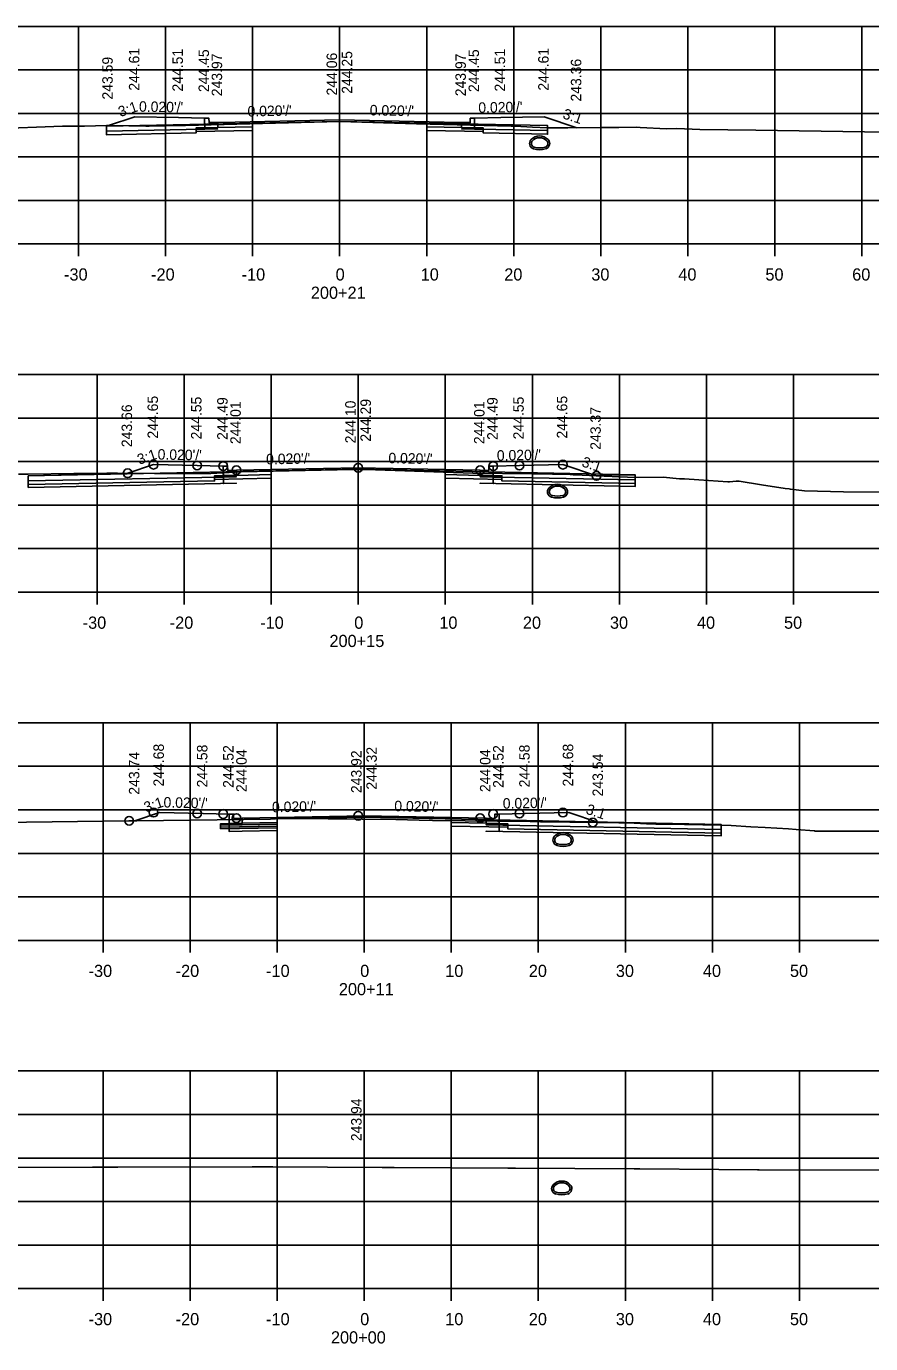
# Model space of a CAD drawing. Extents: x 1369627 to 1374022, y 380035 to 398173.
# Drawn here: x 1372516.6 to 1372613.6, y 380056.4 to 380207.8 of the extents above; entities that cross this region are included whole.
import ezdxf

# ---------------------------------------------------------------- set-up
doc = ezdxf.new("R2010")
doc.units = 0
for name, color, linetype in [('Default', 7, 'Continuous'), ('R_Alt Surface', 7, 'Continuous'), ('R_Axis', 7, 'Continuous'), ('R_Axis Annot', 7, 'Continuous'), ('R_Drive', 7, 'Continuous'), ('R_Exist Surface', 7, 'Continuous'), ('R_Fin Surface', 7, 'Continuous'), ('R_Grid', 7, 'Continuous'), ('R_No Plot', 7, 'Continuous'), ('R_Xsect Elev', 7, 'Continuous'), ('R_Xsect Slope', 7, 'Continuous')]:
    doc.layers.add(name, color=color, linetype=linetype)

msp = doc.modelspace()

# ---------------------------------------------------------------- linework, layer by layer
at = {"layer": 'Default'}
for points in [[(1372537.09, 380197.21), (1372537.59, 380197.21), (1372537.6, 380196.71), (1372538.6, 380196.73), (1372538.6, 380196.14), (1372537.1, 380196.11)], [(1372567.6, 380196.71), (1372567.61, 380197.21), (1372568.11, 380197.21), (1372568.1, 380196.11), (1372566.6, 380196.14), (1372566.6, 380196.73)], [(1372539.23, 380157.25), (1372539.73, 380157.25), (1372539.74, 380156.75), (1372540.74, 380156.77), (1372540.74, 380156.18), (1372539.24, 380156.15)], [(1372569.74, 380156.75), (1372569.75, 380157.25), (1372570.25, 380157.25), (1372570.24, 380156.15), (1372568.74, 380156.18), (1372568.74, 380156.77)], [(1372539.91, 380117.28), (1372540.41, 380117.28), (1372540.42, 380116.78), (1372541.42, 380116.8), (1372541.42, 380116.21), (1372539.92, 380116.18)], [(1372570.42, 380116.78), (1372570.43, 380117.28), (1372570.93, 380117.28), (1372570.92, 380116.18), (1372569.42, 380116.21), (1372569.42, 380116.8)]]:
    msp.add_lwpolyline(points, close=True, dxfattribs=at)
at = {"layer": 'R_Alt Surface'}
for points in [[(1372537.09, 380197.21), (1372537.1, 380195.94), (1372538.6, 380195.97), (1372525.81, 380195.72), (1372525.81, 380196.3), (1372552.6, 380196.84), (1372576.48, 380196.36), (1372576.48, 380195.78), (1372566.6, 380195.97), (1372568.1, 380195.94), (1372568.11, 380197.21)], [(1372537.09, 380197.21), (1372537.1, 380196.11), (1372538.6, 380196.14), (1372542.6, 380196.22), (1372542.6, 380196.64), (1372552.6, 380196.84), (1372562.6, 380196.64), (1372562.6, 380196.22), (1372566.6, 380196.14), (1372568.1, 380196.11), (1372568.11, 380197.21)], [(1372539.23, 380157.25), (1372539.24, 380155.24), (1372540.74, 380155.27), (1372516.83, 380154.79), (1372516.83, 380156.12), (1372554.74, 380156.88), (1372586.55, 380156.24), (1372586.55, 380154.91), (1372568.74, 380155.27), (1372570.24, 380155.24), (1372570.25, 380157.25)], [(1372539.23, 380157.25), (1372539.24, 380155.99), (1372540.74, 380156.02), (1372516.83, 380155.54), (1372516.83, 380156.12), (1372554.74, 380156.88), (1372586.55, 380156.24), (1372586.55, 380155.66), (1372568.74, 380156.02), (1372570.24, 380155.99), (1372570.25, 380157.25)], [(1372539.23, 380157.25), (1372539.24, 380156.15), (1372540.74, 380156.18), (1372544.74, 380156.26), (1372544.74, 380156.68), (1372554.74, 380156.88), (1372564.74, 380156.68), (1372564.74, 380156.26), (1372568.74, 380156.18), (1372570.24, 380156.15), (1372570.25, 380157.25)], [(1372539.91, 380117.28), (1372539.92, 380115.27), (1372541.42, 380115.3), (1372545.42, 380115.38), (1372545.42, 380116.71), (1372555.42, 380116.91), (1372596.41, 380116.09), (1372596.41, 380114.76), (1372569.42, 380115.3), (1372570.92, 380115.27), (1372570.93, 380117.28)], [(1372539.91, 380117.28), (1372539.92, 380116.02), (1372541.42, 380116.05), (1372545.42, 380116.13), (1372545.42, 380116.71), (1372555.42, 380116.91), (1372596.41, 380116.09), (1372596.41, 380115.51), (1372569.42, 380116.05), (1372570.92, 380116.02), (1372570.93, 380117.28)], [(1372539.91, 380117.28), (1372539.92, 380116.18), (1372541.42, 380116.21), (1372545.42, 380116.29), (1372545.42, 380116.71), (1372555.42, 380116.91), (1372565.42, 380116.71), (1372565.42, 380116.29), (1372569.42, 380116.21), (1372570.92, 380116.18), (1372570.93, 380117.28)]]:
    msp.add_lwpolyline(points, dxfattribs=at)
for points in [[(1372525.81, 380195.72), (1372538.6, 380195.97), (1372537.1, 380195.94), (1372536.1, 380195.92), (1372536.1, 380195.51), (1372525.81, 380195.3)], [(1372542.6, 380196.22), (1372538.6, 380196.14), (1372537.1, 380196.11), (1372536.1, 380196.09), (1372536.1, 380195.67), (1372542.6, 380195.8)], [(1372552.6, 380197.01), (1372540.6, 380196.77), (1372538.6, 380196.73), (1372538.6, 380196.14), (1372542.6, 380196.22), (1372542.6, 380196.64), (1372552.6, 380196.84), (1372562.6, 380196.64), (1372562.6, 380196.22), (1372566.6, 380196.14), (1372566.6, 380196.73), (1372564.6, 380196.77)], [(1372562.6, 380196.22), (1372566.6, 380196.14), (1372568.1, 380196.11), (1372569.1, 380196.09), (1372569.1, 380195.67), (1372562.6, 380195.8)], [(1372576.48, 380195.78), (1372566.6, 380195.97), (1372568.1, 380195.94), (1372569.1, 380195.92), (1372569.1, 380195.51), (1372576.48, 380195.36)], [(1372554.74, 380157.05), (1372542.74, 380156.81), (1372540.74, 380156.77), (1372540.74, 380156.18), (1372544.74, 380156.26), (1372544.74, 380156.68), (1372554.74, 380156.88), (1372564.74, 380156.68), (1372564.74, 380156.26), (1372568.74, 380156.18), (1372568.74, 380156.77), (1372566.74, 380156.81)], [(1372516.83, 380155.54), (1372540.74, 380156.02), (1372539.24, 380155.99), (1372538.24, 380155.97), (1372538.24, 380155.55), (1372516.83, 380155.12)], [(1372544.74, 380156.26), (1372540.74, 380156.18), (1372539.24, 380156.15), (1372538.24, 380156.13), (1372538.24, 380155.72), (1372544.74, 380155.85)], [(1372564.74, 380156.26), (1372568.74, 380156.18), (1372570.24, 380156.15), (1372571.24, 380156.13), (1372571.24, 380155.72), (1372564.74, 380155.85)], [(1372586.55, 380155.66), (1372568.74, 380156.02), (1372570.24, 380155.99), (1372571.24, 380155.97), (1372571.24, 380155.55), (1372586.55, 380155.24)], [(1372555.42, 380117.08), (1372543.42, 380116.84), (1372541.42, 380116.8), (1372541.42, 380116.21), (1372545.42, 380116.29), (1372545.42, 380116.71), (1372555.42, 380116.91), (1372565.42, 380116.71), (1372565.42, 380116.29), (1372569.42, 380116.21), (1372569.42, 380116.8), (1372567.42, 380116.84)], [(1372545.42, 380116.29), (1372541.42, 380116.21), (1372539.92, 380116.18), (1372538.92, 380116.16), (1372538.92, 380115.75), (1372545.42, 380115.88)], [(1372545.42, 380116.13), (1372541.42, 380116.05), (1372539.92, 380116.02), (1372538.92, 380116), (1372538.92, 380115.58), (1372545.42, 380115.71)], [(1372565.42, 380116.29), (1372569.42, 380116.21), (1372570.92, 380116.18), (1372571.92, 380116.16), (1372571.92, 380115.75), (1372565.42, 380115.88)], [(1372596.41, 380115.51), (1372569.42, 380116.05), (1372570.92, 380116.02), (1372571.92, 380116), (1372571.92, 380115.58), (1372596.41, 380115.09)]]:
    msp.add_lwpolyline(points, close=True, dxfattribs=at)
at = {"layer": 'R_Axis'}
for p, q in [((1372402.6, 380182.76), (1372702.6, 380182.76)), ((1372522.6, 380181.36), (1372522.6, 380182.76)), ((1372532.6, 380181.36), (1372532.6, 380182.76)), ((1372542.6, 380181.36), (1372542.6, 380182.76)), ((1372552.6, 380181.36), (1372552.6, 380182.76)), ((1372562.6, 380181.36), (1372562.6, 380182.76)), ((1372572.6, 380181.36), (1372572.6, 380182.76)), ((1372582.6, 380181.36), (1372582.6, 380182.76)), ((1372592.6, 380181.36), (1372592.6, 380182.76)), ((1372602.6, 380181.36), (1372602.6, 380182.76)), ((1372612.6, 380181.36), (1372612.6, 380182.76)), ((1372404.74, 380142.76), (1372704.74, 380142.76)), ((1372524.74, 380141.36), (1372524.74, 380142.76)), ((1372534.74, 380141.36), (1372534.74, 380142.76)), ((1372544.74, 380141.36), (1372544.74, 380142.76)), ((1372554.74, 380141.36), (1372554.74, 380142.76)), ((1372564.74, 380141.36), (1372564.74, 380142.76)), ((1372574.74, 380141.36), (1372574.74, 380142.76)), ((1372584.74, 380141.36), (1372584.74, 380142.76)), ((1372594.74, 380141.36), (1372594.74, 380142.76)), ((1372604.74, 380141.36), (1372604.74, 380142.76)), ((1372405.42, 380102.76), (1372705.42, 380102.76)), ((1372525.42, 380101.36), (1372525.42, 380102.76)), ((1372535.42, 380101.36), (1372535.42, 380102.76)), ((1372545.42, 380101.36), (1372545.42, 380102.76)), ((1372555.42, 380101.36), (1372555.42, 380102.76)), ((1372565.42, 380101.36), (1372565.42, 380102.76)), ((1372575.42, 380101.36), (1372575.42, 380102.76)), ((1372585.42, 380101.36), (1372585.42, 380102.76)), ((1372595.42, 380101.36), (1372595.42, 380102.76)), ((1372605.42, 380101.36), (1372605.42, 380102.76)), ((1372405.42, 380062.76), (1372705.42, 380062.76)), ((1372525.42, 380061.36), (1372525.42, 380062.76)), ((1372535.42, 380061.36), (1372535.42, 380062.76)), ((1372545.42, 380061.36), (1372545.42, 380062.76)), ((1372555.42, 380061.36), (1372555.42, 380062.76)), ((1372565.42, 380061.36), (1372565.42, 380062.76)), ((1372575.42, 380061.36), (1372575.42, 380062.76)), ((1372585.42, 380061.36), (1372585.42, 380062.76)), ((1372595.42, 380061.36), (1372595.42, 380062.76)), ((1372605.42, 380061.36), (1372605.42, 380062.76))]:
    msp.add_line(p, q, dxfattribs=at)
at = {"layer": 'R_Drive'}
for centre, radius, start, end in [((1372575.06, 380194.31), 0.646, 136.3515, 253.9529), ((1372575.57, 380193.82), 1.35, 43.6485, 136.3515), ((1372575.06, 380194.31), 0.438, 136.3515, 253.9529), ((1372575.57, 380193.82), 1.15, 43.6485, 136.3515), ((1372576.09, 380194.31), 0.438, 286.0471, 43.6485), ((1372576.09, 380194.31), 0.646, 286.0471, 43.6485), ((1372575.57, 380196.09), 2.5, 253.9529, 286.0471), ((1372575.57, 380196.09), 2.29, 253.9529, 286.0471), ((1372577.63, 380153.8), 1.35, 43.6485, 136.3515), ((1372577.63, 380153.8), 1.15, 43.6485, 136.3515), ((1372577.12, 380154.29), 0.646, 136.3515, 253.9529), ((1372577.12, 380154.29), 0.438, 136.3515, 253.9529), ((1372577.63, 380156.08), 2.5, 253.9529, 286.0471), ((1372577.63, 380156.08), 2.29, 253.9529, 286.0471), ((1372578.14, 380154.29), 0.438, 286.0471, 43.6485), ((1372578.14, 380154.29), 0.646, 286.0471, 43.6485), ((1372577.75, 380114.28), 0.646, 136.3515, 253.9529), ((1372578.26, 380113.79), 1.35, 43.6485, 136.3515), ((1372577.75, 380114.28), 0.438, 136.3515, 253.9529), ((1372578.26, 380113.79), 1.15, 43.6485, 136.3515), ((1372578.77, 380114.28), 0.438, 286.0471, 43.6485), ((1372578.77, 380114.28), 0.646, 286.0471, 43.6485), ((1372578.26, 380116.06), 2.5, 253.9529, 286.0471), ((1372578.26, 380116.06), 2.29, 253.9529, 286.0471), ((1372577.6, 380074.25), 0.646, 136.3515, 253.9529), ((1372578.12, 380073.77), 1.35, 43.6485, 136.3515), ((1372578.12, 380073.77), 1.15, 43.6485, 136.3515), ((1372578.63, 380074.25), 0.646, 286.0471, 43.6485), ((1372577.6, 380074.25), 0.438, 136.3515, 253.9529), ((1372578.12, 380076.04), 2.5, 253.9529, 286.0471), ((1372578.12, 380076.04), 2.29, 253.9529, 286.0471), ((1372578.63, 380074.25), 0.438, 286.0471, 43.6485)]:
    msp.add_arc(centre, radius, start, end, dxfattribs=at)
at = {"layer": 'R_Exist Surface'}
for points in [[(1372512.73, 380196), (1372520.78, 380196.28), (1372521.71, 380196.29), (1372522.25, 380196.3), (1372523.27, 380196.31), (1372525.81, 380196.35), (1372526.44, 380196.35), (1372530.33, 380196.28), (1372530.71, 380196.29), (1372534.29, 380196.35), (1372534.44, 380196.35), (1372534.5, 380196.35), (1372534.89, 380196.36), (1372552.62, 380196.82), (1372560.16, 380196.61), (1372561.43, 380196.57), (1372572.3, 380196.31), (1372572.77, 380196.28), (1372574.75, 380196.18), (1372576.48, 380196.1), (1372578.8, 380196.11), (1372582.55, 380196.13), (1372584.16, 380196.14), (1372584.69, 380196.14), (1372586.69, 380196.16), (1372587.11, 380196.13), (1372590.13, 380195.99), (1372591.34, 380196.02), (1372593.96, 380195.9), (1372600.42, 380195.85), (1372612.91, 380195.65), (1372621.12, 380195.62)], [(1372515.69, 380156.3), (1372516.83, 380156.33), (1372522.07, 380156.38), (1372524.83, 380156.41), (1372525.86, 380156.42), (1372527.07, 380156.43), (1372531.33, 380156.39), (1372534.71, 380156.37), (1372537.79, 380156.41), (1372541.27, 380156.57), (1372554.16, 380156.85), (1372554.74, 380156.86), (1372554.96, 380156.85), (1372555, 380156.85), (1372555.62, 380156.84), (1372567.89, 380156.44), (1372574.68, 380156.35), (1372574.98, 380156.35), (1372579.07, 380156.28), (1372579.42, 380156.24), (1372580.47, 380156.19), (1372582.11, 380156.12), (1372585.67, 380155.99), (1372586.55, 380155.95), (1372589.78, 380155.96), (1372591.64, 380155.8), (1372591.93, 380155.8), (1372592.02, 380155.79), (1372592.23, 380155.78), (1372593.88, 380155.66), (1372597.18, 380155.45), (1372597.4, 380155.45), (1372598.17, 380155.53), (1372598.48, 380155.51), (1372601.08, 380155.11), (1372603.77, 380154.68), (1372604.23, 380154.64), (1372604.38, 380154.59), (1372605.99, 380154.39), (1372610.5, 380154.3), (1372625.69, 380154.25)], [(1372513.67, 380116.29), (1372528.4, 380116.49), (1372529.13, 380116.5), (1372529.2, 380116.5), (1372529.22, 380116.5), (1372529.23, 380116.5), (1372529.24, 380116.5), (1372529.28, 380116.5), (1372529.31, 380116.5), (1372544.66, 380116.7), (1372545.22, 380116.73), (1372547.41, 380116.77), (1372559.06, 380116.64), (1372561.73, 380116.56), (1372563.26, 380116.53), (1372574.5, 380116.4), (1372575.68, 380116.38), (1372585.76, 380116.26), (1372587.85, 380116.17), (1372588.91, 380116.13), (1372590.42, 380116.1), (1372592.21, 380116.06), (1372596.41, 380116.01), (1372597.57, 380115.95), (1372599.83, 380115.81), (1372601.48, 380115.73), (1372604.15, 380115.57), (1372605.05, 380115.5), (1372607.15, 380115.33), (1372607.24, 380115.3), (1372619.73, 380115.32)], [(1372509.33, 380076.69), (1372524.19, 380076.73), (1372527.13, 380076.73), (1372542.55, 380076.76), (1372544.92, 380076.76), (1372557.5, 380076.69), (1372558.85, 380076.68), (1372571.94, 380076.6), (1372572.79, 380076.59), (1372586.42, 380076.51), (1372586.77, 380076.51), (1372587.1, 380076.51), (1372596.15, 380076.46), (1372600.59, 380076.42), (1372600.78, 380076.42), (1372614.61, 380076.36)]]:
    msp.add_lwpolyline(points, dxfattribs=at)
at = {"layer": 'R_Fin Surface'}
for points in [[(1372525.81, 380196.3), (1372526.03, 380196.35), (1372529.09, 380197.37), (1372534.09, 380197.27), (1372537.09, 380197.21), (1372537.59, 380197.21), (1372537.6, 380196.71), (1372538.6, 380196.73), (1372540.6, 380196.77), (1372552.6, 380197.01), (1372564.6, 380196.77), (1372566.6, 380196.73), (1372567.6, 380196.71), (1372567.61, 380197.21), (1372568.11, 380197.21), (1372571.11, 380197.27), (1372576.11, 380197.37), (1372579.86, 380196.12)], [(1372516.83, 380156.12), (1372522.05, 380156.25), (1372523.09, 380156.28), (1372525.64, 380156.35), (1372526.16, 380156.36), (1372526.6, 380156.37), (1372527.73, 380156.4), (1372528.25, 380156.42), (1372531.23, 380157.41), (1372536.23, 380157.31), (1372539.23, 380157.25), (1372539.73, 380157.25), (1372539.74, 380156.75), (1372540.74, 380156.77), (1372542.74, 380156.81), (1372554.74, 380157.05), (1372566.74, 380156.81), (1372568.74, 380156.77), (1372569.74, 380156.75), (1372569.75, 380157.25), (1372570.25, 380157.25), (1372573.25, 380157.31), (1372578.25, 380157.41), (1372582.1, 380156.12), (1372582.48, 380156.16), (1372583.12, 380156.23), (1372586.55, 380156.24)], [(1372529.09, 380116.5), (1372531.91, 380117.44), (1372536.91, 380117.34), (1372539.91, 380117.28), (1372540.41, 380117.28), (1372540.42, 380116.78), (1372541.42, 380116.8), (1372543.42, 380116.84), (1372555.42, 380117.08), (1372567.42, 380116.84), (1372569.42, 380116.8), (1372570.42, 380116.78), (1372570.43, 380117.28), (1372570.93, 380117.28), (1372573.93, 380117.34), (1372578.93, 380117.44), (1372582.35, 380116.3), (1372596.41, 380116.09)]]:
    msp.add_lwpolyline(points, dxfattribs=at)
at = {"layer": 'R_Grid'}
for p, q in [((1372402.6, 380207.76), (1372702.6, 380207.76)), ((1372522.6, 380182.76), (1372522.6, 380207.76)), ((1372532.6, 380182.76), (1372532.6, 380207.76)), ((1372542.6, 380182.76), (1372542.6, 380207.76)), ((1372552.6, 380182.76), (1372552.6, 380207.76)), ((1372562.6, 380182.76), (1372562.6, 380207.76)), ((1372572.6, 380182.76), (1372572.6, 380207.76)), ((1372582.6, 380182.76), (1372582.6, 380207.76)), ((1372592.6, 380182.76), (1372592.6, 380207.76)), ((1372602.6, 380182.76), (1372602.6, 380207.76)), ((1372612.6, 380182.76), (1372612.6, 380207.76)), ((1372402.6, 380202.76), (1372702.6, 380202.76)), ((1372402.6, 380197.76), (1372702.6, 380197.76)), ((1372402.6, 380192.76), (1372702.6, 380192.76)), ((1372402.6, 380187.76), (1372702.6, 380187.76)), ((1372402.6, 380182.76), (1372702.6, 380182.76)), ((1372404.74, 380167.76), (1372704.74, 380167.76)), ((1372524.74, 380142.76), (1372524.74, 380167.76)), ((1372534.74, 380142.76), (1372534.74, 380167.76)), ((1372544.74, 380142.76), (1372544.74, 380167.76)), ((1372554.74, 380142.76), (1372554.74, 380167.76)), ((1372564.74, 380142.76), (1372564.74, 380167.76)), ((1372574.74, 380142.76), (1372574.74, 380167.76)), ((1372584.74, 380142.76), (1372584.74, 380167.76)), ((1372594.74, 380142.76), (1372594.74, 380167.76)), ((1372604.74, 380142.76), (1372604.74, 380167.76)), ((1372404.74, 380162.76), (1372704.74, 380162.76)), ((1372404.74, 380157.76), (1372704.74, 380157.76)), ((1372404.74, 380152.76), (1372704.74, 380152.76)), ((1372404.74, 380147.76), (1372704.74, 380147.76)), ((1372404.74, 380142.76), (1372704.74, 380142.76)), ((1372405.42, 380127.76), (1372705.42, 380127.76)), ((1372525.42, 380102.76), (1372525.42, 380127.76)), ((1372535.42, 380102.76), (1372535.42, 380127.76)), ((1372545.42, 380102.76), (1372545.42, 380127.76)), ((1372555.42, 380102.76), (1372555.42, 380127.76)), ((1372565.42, 380102.76), (1372565.42, 380127.76)), ((1372575.42, 380102.76), (1372575.42, 380127.76)), ((1372585.42, 380102.76), (1372585.42, 380127.76)), ((1372595.42, 380102.76), (1372595.42, 380127.76)), ((1372605.42, 380102.76), (1372605.42, 380127.76)), ((1372405.42, 380122.76), (1372705.42, 380122.76)), ((1372405.42, 380117.76), (1372705.42, 380117.76)), ((1372405.42, 380112.76), (1372705.42, 380112.76)), ((1372405.42, 380107.76), (1372705.42, 380107.76)), ((1372405.42, 380102.76), (1372705.42, 380102.76)), ((1372405.42, 380087.76), (1372705.42, 380087.76)), ((1372525.42, 380062.76), (1372525.42, 380087.76)), ((1372535.42, 380062.76), (1372535.42, 380087.76)), ((1372545.42, 380062.76), (1372545.42, 380087.76)), ((1372555.42, 380062.76), (1372555.42, 380087.76)), ((1372565.42, 380062.76), (1372565.42, 380087.76)), ((1372575.42, 380062.76), (1372575.42, 380087.76)), ((1372585.42, 380062.76), (1372585.42, 380087.76)), ((1372595.42, 380062.76), (1372595.42, 380087.76)), ((1372605.42, 380062.76), (1372605.42, 380087.76)), ((1372405.42, 380082.76), (1372705.42, 380082.76)), ((1372405.42, 380077.76), (1372705.42, 380077.76)), ((1372405.42, 380072.76), (1372705.42, 380072.76)), ((1372405.42, 380067.76), (1372705.42, 380067.76)), ((1372405.42, 380062.76), (1372705.42, 380062.76))]:
    msp.add_line(p, q, dxfattribs=at)
at = {"layer": 'R_No Plot'}
for centre in [(1372531.23, 380157.41), (1372578.25, 380157.41), (1372528.25, 380156.42), (1372536.23, 380157.31), (1372539.23, 380157.25), (1372540.74, 380156.77), (1372554.74, 380157.05), (1372568.74, 380156.77), (1372570.25, 380157.25), (1372573.25, 380157.31), (1372582.1, 380156.12), (1372531.23, 380117.44), (1372536.23, 380117.34), (1372539.23, 380117.28), (1372540.74, 380116.8), (1372554.74, 380117.08), (1372568.74, 380116.8), (1372570.25, 380117.28), (1372573.25, 380117.34), (1372578.25, 380117.44), (1372528.41, 380116.5), (1372581.67, 380116.3)]:
    msp.add_circle(centre, 0.5, dxfattribs=at)
at = {"layer": 'R_Xsect Elev'}
for p, q in [((1372552.6, 380196.82), (1372552.6, 380206.82)), ((1372554.74, 380156.86), (1372554.74, 380166.86)), ((1372555.42, 380116.68), (1372555.42, 380126.68)), ((1372555.42, 380076.7), (1372555.42, 380086.7))]:
    msp.add_line(p, q, dxfattribs=at)

# ---------------------------------------------------------------- texts
at = {"layer": 'R_Axis Annot'}
for s, p in [('-30', (1372520.94, 380178.56)), ('-20', (1372530.94, 380178.56)), ('-10', (1372541.34, 380178.56)), ('0', (1372552.14, 380178.56)), ('10', (1372561.91, 380178.56)), ('20', (1372571.51, 380178.56)), ('30', (1372581.51, 380178.56)), ('40', (1372591.51, 380178.56)), ('50', (1372601.51, 380178.56)), ('60', (1372611.48, 380178.56)), ('200+21', (1372549.29, 380176.46)), ('-30', (1372523.08, 380138.56)), ('-20', (1372533.08, 380138.56)), ('-10', (1372543.47, 380138.56)), ('0', (1372554.28, 380138.56)), ('10', (1372564.05, 380138.56)), ('20', (1372573.65, 380138.56)), ('30', (1372583.65, 380138.56)), ('40', (1372593.65, 380138.56)), ('50', (1372603.65, 380138.56)), ('200+15', (1372551.43, 380136.46)), ('-30', (1372523.76, 380098.56)), ('-20', (1372533.76, 380098.56)), ('-10', (1372544.15, 380098.56)), ('0', (1372554.96, 380098.56)), ('10', (1372564.73, 380098.56)), ('20', (1372574.33, 380098.56)), ('30', (1372584.33, 380098.56)), ('40', (1372594.33, 380098.56)), ('50', (1372604.33, 380098.56)), ('200+11', (1372552.51, 380096.46)), ('-30', (1372523.76, 380058.56)), ('-20', (1372533.76, 380058.56)), ('-10', (1372544.15, 380058.56)), ('0', (1372554.96, 380058.56)), ('10', (1372564.73, 380058.56)), ('20', (1372574.33, 380058.56)), ('30', (1372584.33, 380058.56)), ('40', (1372594.33, 380058.56)), ('50', (1372604.33, 380058.56)), ('200+00', (1372551.6, 380056.46))]:
    msp.add_text(s, height=1.4, dxfattribs=at).set_placement(p)
at = {"layer": 'R_Xsect Elev'}
for s, p in [('244.61', (1372529.59, 380200.37)), ('244.51', (1372534.59, 380200.27)), ('244.45', (1372537.59, 380200.21)), ('244.25', (1372554.05, 380200.01)), ('244.45', (1372568.61, 380200.21)), ('244.51', (1372571.61, 380200.27)), ('244.61', (1372576.61, 380200.37)), ('243.59', (1372526.53, 380199.35)), ('243.97', (1372539.1, 380199.73)), ('244.06', (1372552.3, 380199.82)), ('243.97', (1372567.1, 380199.73)), ('243.36', (1372580.36, 380199.12)), ('243.66', (1372528.75, 380159.42)), ('244.65', (1372531.73, 380160.41)), ('244.55', (1372536.73, 380160.31)), ('244.49', (1372539.73, 380160.25)), ('244.01', (1372541.24, 380159.77)), ('244.10', (1372554.44, 380159.86)), ('244.29', (1372556.19, 380160.05)), ('244.01', (1372569.24, 380159.77)), ('244.49', (1372570.75, 380160.25)), ('244.55', (1372573.75, 380160.31)), ('244.65', (1372578.75, 380160.41)), ('243.37', (1372582.6, 380159.12)), ('244.68', (1372532.41, 380120.44)), ('244.58', (1372537.41, 380120.34)), ('244.52', (1372540.41, 380120.28)), ('244.04', (1372541.92, 380119.8)), ('244.32', (1372556.87, 380120.08)), ('244.04', (1372569.92, 380119.8)), ('244.52', (1372571.43, 380120.28)), ('244.58', (1372574.43, 380120.34)), ('244.68', (1372579.43, 380120.44)), ('243.74', (1372529.59, 380119.5)), ('243.92', (1372555.12, 380119.68)), ('243.54', (1372582.85, 380119.3)), ('243.94', (1372555.12, 380079.7))]:
    msp.add_text(s, height=1.2, rotation=90, dxfattribs=at).set_placement(p)
at = {"layer": 'R_Xsect Slope'}
for s, rotation, p in [('3:1', 18.4332, (1372527.4, 380197.33)), ("0.020'/'", 358.8542, (1372529.54, 380197.96)), ("0.020'/'", 1.1458, (1372542.03, 380197.4)), ("0.020'/'", 358.8542, (1372556.05, 380197.54)), ("0.020'/'", 1.1458, (1372568.54, 380197.82)), ('3:1', 341.5668, (1372578.14, 380197.22)), ('3:1', 18.4332, (1372529.58, 380157.39)), ("0.020'/'", 358.8542, (1372531.68, 380158)), ("0.020'/'", 1.1458, (1372544.16, 380157.44)), ("0.020'/'", 358.8542, (1372558.19, 380157.58)), ("0.020'/'", 1.1458, (1372570.67, 380157.86)), ('3:1', 341.5668, (1372580.33, 380157.24)), ('3:1', 18.4332, (1372530.34, 380117.44)), ("0.020'/'", 358.8542, (1372532.36, 380118.03)), ("0.020'/'", 1.1458, (1372544.84, 380117.47)), ("0.020'/'", 358.8542, (1372558.87, 380117.61)), ("0.020'/'", 1.1458, (1372571.35, 380117.89)), ('3:1', 341.5668, (1372580.8, 380117.34))]:
    msp.add_text(s, height=1.2, rotation=rotation, dxfattribs=at).set_placement(p)

doc.saveas('drawing.dxf')
